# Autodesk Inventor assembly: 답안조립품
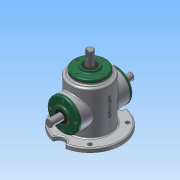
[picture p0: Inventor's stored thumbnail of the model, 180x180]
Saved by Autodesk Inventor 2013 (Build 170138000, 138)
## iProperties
Created: 2018-04
Part Number: 답안조립품
Document SubType Name: Assembly
Designer: Administrator
Author: Administrator
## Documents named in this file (16)
- C:\Users\Administrator\Desktop\480408V1006\답안조립품.iam
- C:\Users\Administrator\Desktop\480408V1006\본체.ipt
- C:\Users\Administrator\Desktop\480408V1006\메인 축.ipt
- 메인 축.ipt
- C:\Users\Administrator\Desktop\480408V1006\서브 축.ipt
- 서브 축.ipt
- C:\Users\Administrator\Desktop\480408V1006\커버.ipt
- C:\Users\Administrator\Desktop\480408V1006\베어링 6203.ipt
- C:\Users\Administrator\Desktop\480408V1006\오일 실.ipt
- 오일 실.ipt
- C:\Users\Administrator\Desktop\480408V1006\키 5x5.ipt
- C:\Users\Administrator\Desktop\480408V1006\키 4x4.ipt
- C:\Users\Administrator\Desktop\480408V1006\메인 베벨기어.ipt
- C:\Users\Administrator\Desktop\480408V1006\서브 베벨기어.ipt
- C:\Users\Administrator\Desktop\480408V1006\볼트 M4.ipt
- 볼트 M4.ipt
